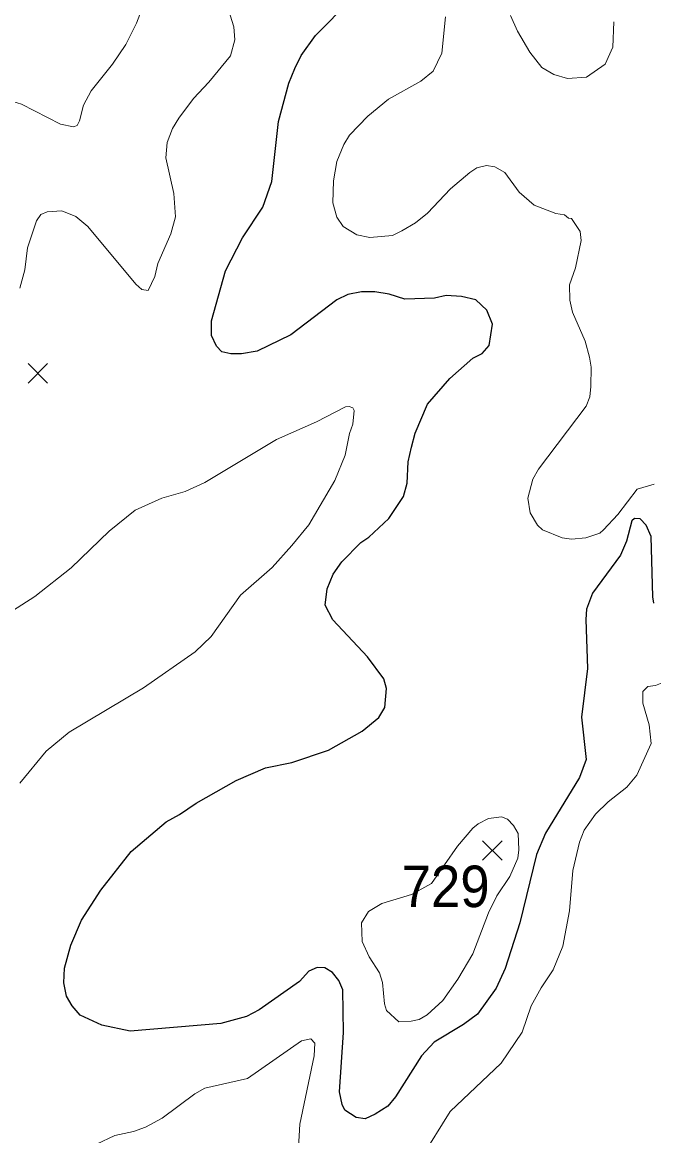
# Model space of a CAD drawing. Extents: x 294.2 to 320.3, y 7482.7 to 7510.7.
# Drawn here: x 304.291 to 305.508, y 7503.14 to 7505.286 of the extents above; entities that cross this region are included whole.
import ezdxf
from ezdxf.enums import TextEntityAlignment as Align

# ---------------------------------------------------------------- set-up
doc = ezdxf.new("R2010")
doc.units = 0
doc.header["$LTSCALE"] = 0.032
for name, color, linetype, lineweight in [('1', 7, 'Continuous', 25), ('2', 7, 'Continuous', 13), ('21', 7, 'Continuous', 25)]:
    doc.layers.add(name, color=color, linetype=linetype, lineweight=lineweight)
doc.layers.add('61', color=7, linetype='Continuous')

msp = doc.modelspace()

# ---------------------------------------------------------------- linework, layer by layer
at = {"layer": '1'}
for points in [[(304.8054, 7505.169), (304.8166, 7505.1973), (304.8292, 7505.2225), (304.8567, 7505.261), (304.9246, 7505.3302)], [(304.6563, 7504.7105), (304.6834, 7504.8072), (304.7156, 7504.8709), (304.7552, 7504.9299), (304.7725, 7504.9795), (304.7855, 7505.0951), (304.8054, 7505.169)], [(305.3779, 7504.1347), (305.3805, 7504.0404), (305.3691, 7503.9468), (305.3785, 7503.865), (305.3652, 7503.8304), (305.2999, 7503.7233), (305.2824, 7503.6819), (305.2502, 7503.5501), (305.2219, 7503.462), (305.2046, 7503.4243), (305.1688, 7503.374), (305.1421, 7503.3543), (305.0855, 7503.3205), (305.0611, 7503.2938), (305.011, 7503.2151), (304.9961, 7503.1971), (304.9717, 7503.1813), (304.9521, 7503.1727), (304.9348, 7503.175), (304.913, 7503.1892), (304.908, 7503.2002), (304.9028, 7503.2245), (304.9105, 7503.3387), (304.9093, 7503.4209), (304.9014, 7503.439), (304.8896, 7503.4548), (304.8743, 7503.4634), (304.8601, 7503.4642), (304.8436, 7503.4571), (304.8255, 7503.4374), (304.7481, 7503.3824), (304.7238, 7503.3698), (304.6742, 7503.3564), (304.4991, 7503.3415), (304.4445, 7503.3533), (304.4028, 7503.3722), (304.3879, 7503.3903), (304.3769, 7503.4091), (304.3714, 7503.4343), (304.373, 7503.4626), (304.3852, 7503.5074), (304.4056, 7503.5554), (304.443, 7503.6131), (304.5014, 7503.6878), (304.5685, 7503.7452), (304.5947, 7503.7589), (304.6269, 7503.7809), (304.7036, 7503.8249), (304.7602, 7503.8493), (304.8109, 7503.8595), (304.8817, 7503.883), (304.9463, 7503.92), (304.9786, 7503.9459), (304.9904, 7503.9656), (304.9935, 7504.0017), (304.9884, 7504.0206), (304.957, 7504.0631), (304.8901, 7504.1346), (304.8753, 7504.1629), (304.8788, 7504.1939), (304.8906, 7504.2226), (304.9071, 7504.2462), (304.944, 7504.2832), (304.9592, 7504.2934), (304.9981, 7504.3296), (305.0264, 7504.3721), (305.0334, 7504.398), (305.0354, 7504.4389), (305.0417, 7504.4672), (305.0488, 7504.4939), (305.0724, 7504.5498), (305.1152, 7504.5993), (305.16, 7504.6386), (305.1781, 7504.648), (305.1915, 7504.663), (305.1977, 7504.7046), (305.1868, 7504.7315), (305.1656, 7504.7512), (305.1381, 7504.7574), (305.1082, 7504.7598), (305.0858, 7504.7543), (305.0285, 7504.7527), (304.9986, 7504.7622), (304.9711, 7504.7669), (304.9455, 7504.7669), (304.9187, 7504.7614), (304.8975, 7504.7512), (304.8089, 7504.6836), (304.744, 7504.6523), (304.7141, 7504.6468), (304.6933, 7504.6468), (304.676, 7504.6508), (304.6657, 7504.6618), (304.6563, 7504.6822), (304.6563, 7504.7105)], [(305.4711, 7504.3297), (305.4663, 7504.325), (305.4561, 7504.2857), (305.4443, 7504.259), (305.3905, 7504.1858), (305.3787, 7504.1551), (305.3779, 7504.1347)], [(305.5085, 7504.1662), (305.5069, 7504.1788), (305.5033, 7504.2951), (305.4939, 7504.3171), (305.4821, 7504.3289), (305.4711, 7504.3297)]]:
    msp.add_lwpolyline(points, dxfattribs=at)
at = {"layer": '2'}
for points in [[(304.6793, 7505.3417), (304.6992, 7505.2772), (304.7011, 7505.2523), (304.6928, 7505.2216), (304.6513, 7505.1705), (304.6213, 7505.1392), (304.5932, 7505.1016), (304.581, 7505.0812), (304.5708, 7505.0544), (304.5682, 7505.025), (304.5836, 7504.956), (304.5868, 7504.9113), (304.5779, 7504.8781), (304.5529, 7504.8213), (304.5472, 7504.7964), (304.5338, 7504.7695), (304.5217, 7504.7708)], [(304.4016, 7505.0965), (304.4093, 7505.1265), (304.424, 7505.154), (304.4655, 7505.2057), (304.491, 7505.2433), (304.5115, 7505.2842), (304.5178, 7505.3014)], [(305.3459, 7504.7798), (305.3574, 7504.813), (305.3689, 7504.8654), (305.3664, 7504.8832), (305.3498, 7504.9081), (305.344, 7504.9087), (305.3364, 7504.9151), (305.3197, 7504.9179), (305.2778, 7504.9334), (305.2491, 7504.9585), (305.2215, 7504.9969), (305.202, 7505.0075), (305.1859, 7505.0103), (305.1675, 7505.0055), (305.1538, 7504.9969), (305.1167, 7504.9649), (305.0727, 7504.9183), (305.0491, 7504.8998), (305.0229, 7504.8845), (305.005, 7504.8755), (304.9616, 7504.8711), (304.9361, 7504.8768), (304.9098, 7504.8928), (304.8977, 7504.9107), (304.89, 7504.9381), (304.8913, 7504.9803), (304.898, 7505.0176), (304.9111, 7505.0505), (304.922, 7505.0684), (304.9577, 7505.1054), (304.9973, 7505.138), (305.0598, 7505.1727), (305.0834, 7505.1917), (305.1, 7505.2267), (305.1069, 7505.2966)], [(305.2327, 7505.2991), (305.2459, 7505.269), (305.2694, 7505.2289), (305.293, 7505.1992), (305.3159, 7505.1858), (305.3423, 7505.1781), (305.3791, 7505.1803), (305.4147, 7505.2056), (305.4297, 7505.2384), (305.4314, 7505.2874)], [(304.2421, 7505.1358), (304.2731, 7505.1333), (304.2899, 7505.1284), (304.3653, 7505.0901), (304.3901, 7505.0844), (304.3972, 7505.0875), (304.4016, 7505.0965)], [(304.5217, 7504.7708), (304.5102, 7504.7811), (304.4176, 7504.8928), (304.3946, 7504.912), (304.3678, 7504.9228), (304.3397, 7504.9209), (304.3269, 7504.9158)], [(304.3269, 7504.9158), (304.3186, 7504.9037), (304.3014, 7504.8513), (304.2963, 7504.8092), (304.2867, 7504.7734)], [(305.3874, 7504.5844), (305.3881, 7504.6215), (305.3849, 7504.6406), (305.376, 7504.6713), (305.3517, 7504.7275), (305.3466, 7504.7504), (305.3459, 7504.7798)], [(305.5094, 7504.3961), (305.4768, 7504.3859), (305.4391, 7504.3373), (305.4117, 7504.308), (305.4043, 7504.3015), (305.3779, 7504.2926), (305.3498, 7504.2901), (305.3319, 7504.2926), (305.2942, 7504.308), (305.2846, 7504.3169), (305.2706, 7504.3405), (305.2661, 7504.3686), (305.2757, 7504.4057), (305.2866, 7504.4248), (305.3785, 7504.5461), (305.3855, 7504.564), (305.3874, 7504.5844)], [(304.2657, 7504.1471), (304.3155, 7504.1796), (304.3857, 7504.2345), (304.4591, 7504.3054), (304.5089, 7504.3456), (304.5606, 7504.3686), (304.6053, 7504.382), (304.6436, 7504.3992), (304.7815, 7504.4822), (304.8582, 7504.5161), (304.9143, 7504.5448), (304.9213, 7504.5455), (304.9284, 7504.5429), (304.9309, 7504.5378), (304.9283, 7504.5116), (304.922, 7504.4938), (304.9137, 7504.4516), (304.8939, 7504.4031), (304.8435, 7504.3176), (304.8109, 7504.2779), (304.7732, 7504.2354), (304.7118, 7504.1819), (304.6555, 7504.102), (304.6244, 7504.0724), (304.5249, 7504.0034), (304.3819, 7503.9178), (304.3372, 7503.8814), (304.2867, 7503.8195)], [(305.5037, 7503.8961), (305.4998, 7503.9319), (305.4877, 7503.974), (305.4877, 7503.9964), (305.4973, 7504.0059), (305.512, 7504.0079), (305.5311, 7504.0155)], [(305.0605, 7503.0967), (305.1161, 7503.1868), (305.2144, 7503.28), (305.2546, 7503.3394), (305.2725, 7503.3905), (305.2917, 7503.425), (305.3147, 7503.4594), (305.3332, 7503.5054), (305.3459, 7503.5731), (305.3523, 7503.651), (305.3657, 7503.7059), (305.3747, 7503.7289), (305.3964, 7503.7595), (305.4206, 7503.7837), (305.4564, 7503.8118), (305.4762, 7503.8348), (305.5037, 7503.8961)], [(304.4342, 7503.1236), (304.47, 7503.1402), (304.5057, 7503.1478), (304.5287, 7503.1562), (304.5613, 7503.174), (304.6238, 7503.2206), (304.6436, 7503.2315), (304.7254, 7503.25), (304.8294, 7503.3228), (304.8479, 7503.3266), (304.8556, 7503.3183), (304.8543, 7503.2941), (304.8262, 7503.1619), (304.8236, 7503.1172)]]:
    msp.add_lwpolyline(points, dxfattribs=at)
msp.add_lwpolyline([(304.98, 7503.4536), (304.9597, 7503.485), (304.9462, 7503.5143), (304.945, 7503.5501), (304.959, 7503.5718), (304.9846, 7503.5878), (305.0414, 7503.605), (305.0803, 7503.626), (305.1301, 7503.6982), (305.1595, 7503.7327), (305.1703, 7503.741), (305.1902, 7503.7512), (305.215, 7503.7544), (305.2265, 7503.7499), (305.238, 7503.7378), (305.2469, 7503.7222), (305.2486, 7503.691), (305.2464, 7503.6749), (305.231, 7503.6395), (305.2061, 7503.6024), (305.1901, 7503.5693), (305.1595, 7503.4907), (305.1308, 7503.4416), (305.102, 7503.4007), (305.072, 7503.3732), (305.0561, 7503.3636), (305.0408, 7503.3605), (305.0171, 7503.3592), (304.9935, 7503.3815), (304.9896, 7503.3943), (304.9858, 7503.4352)], close=True, dxfattribs=at)
at = {"layer": '21'}
for p, q in [((304.3028, 7504.6283), (304.3403, 7504.5908)), ((304.3403, 7504.6283), (304.3028, 7504.5908)), ((305.1787, 7503.7084), (305.2162, 7503.6709)), ((305.2162, 7503.7084), (305.1787, 7503.6709))]:
    msp.add_line(p, q, dxfattribs=at)

# ---------------------------------------------------------------- texts
at = {"layer": '61', "width": 0.95}
msp.add_text('729', height=0.08, dxfattribs=at).set_placement((305.1074, 7503.5806), align=Align.CENTER)

doc.saveas('drawing.dxf')
